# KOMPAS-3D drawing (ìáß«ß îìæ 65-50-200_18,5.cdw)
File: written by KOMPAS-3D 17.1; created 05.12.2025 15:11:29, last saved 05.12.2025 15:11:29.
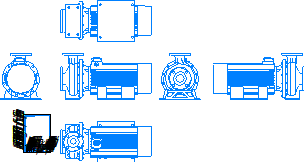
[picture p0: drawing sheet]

Sheet 1: A4, portrait

Title block, sheet 1: name: Насос МНС / 65-50-200_18,5; material: Сталь 10  ГОСТ 1050-88; mass: 210,9; sheets: 1; sheet format: A4

Views: Вид 1, Спереди, Проекционный вид 2, Проекционный вид 4, Проекционный вид 5, Проекционный вид 6
Referenced files in \\adlc.lan\data\АДЛ_ПКД\3D-модели\ADL production\Насосы ГРАНПАМП\Насосы ГРАНПАМП серии МНС\KOMPAS 3D\: Насос МНС 65-50-200_18,5.m3d
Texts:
  Andrey
  АДЛ
Dimensions and other numbers on the sheet: 1:1; 1; 65-50-200_18,5; 210,9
